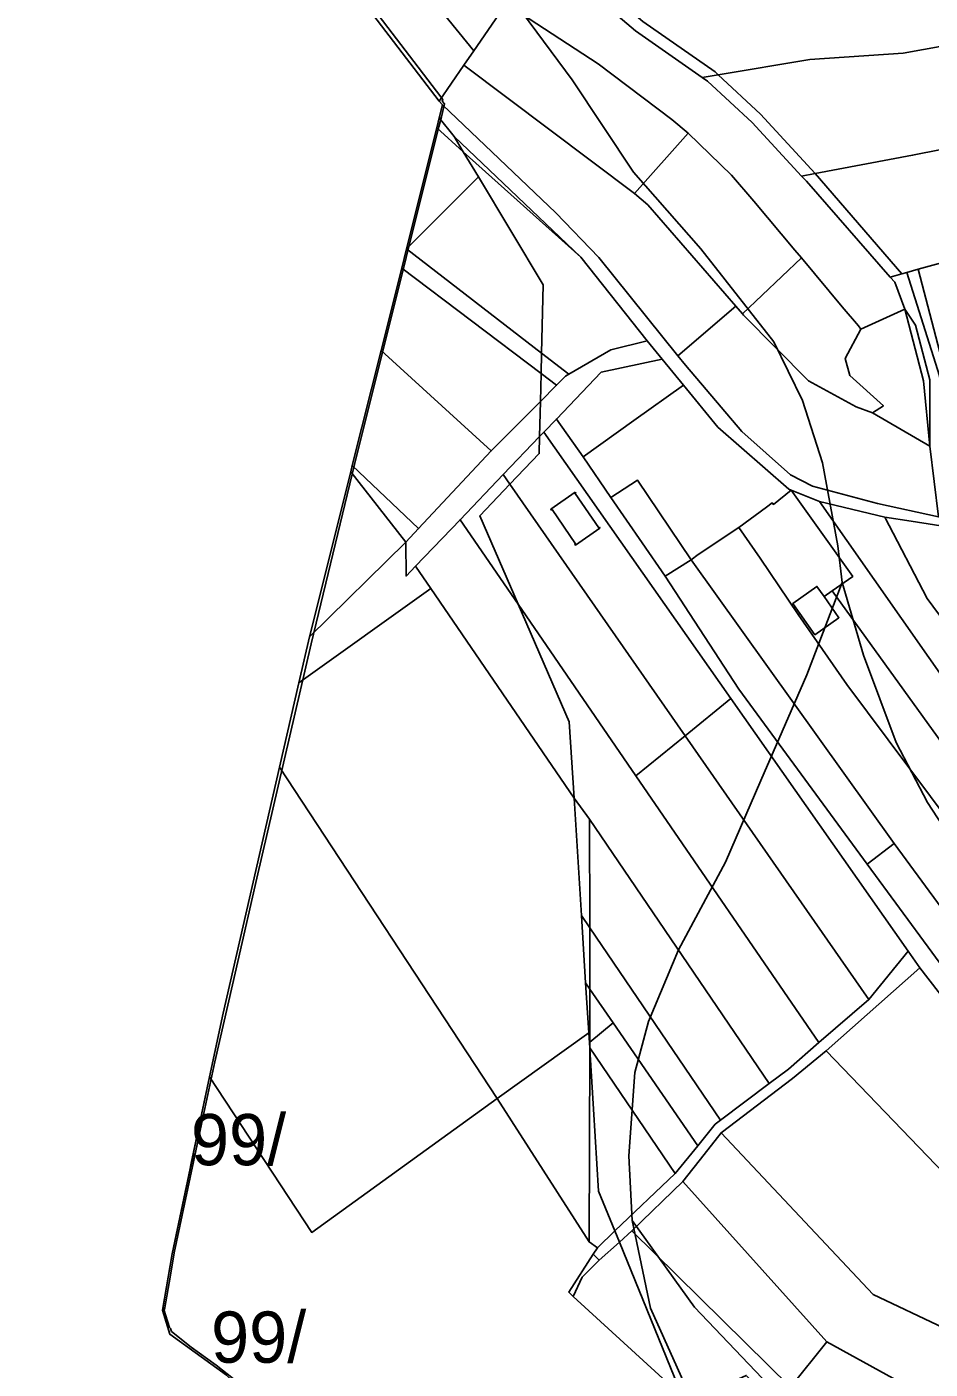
# Model space of a CAD drawing. Extents: x -535894 to -532827, y -1165802 to -1163635.
# Drawn here: x -535269.9 to -535005.1, y -1165464.5 to -1165071.2 of the extents above; entities that cross this region are included whole.
import ezdxf

# ---------------------------------------------------------------- set-up
doc = ezdxf.new("R2010")
doc.units = 0
for name, color, linetype in [('BPEJ_s', 7, 'Continuous'), ('orna_s', 7, 'Continuous'), ('ostatni_s', 7, 'Continuous'), ('sad_s', 7, 'Continuous'), ('trav_porost_s', 7, 'Continuous'), ('zahrada_s', 7, 'Continuous')]:
    doc.layers.add(name, color=color, linetype=linetype)

msp = doc.modelspace()

# ---------------------------------------------------------------- linework, layer by layer
at = {"layer": 'BPEJ_s'}
for points in [[(-535269.853, -1164932.956), (-535148.539, -1165091.751), (-535147.971, -1165092.495), (-535148.097, -1165093.014), (-535147.427, -1165093.765), (-535148.373, -1165097.563), (-535149.117, -1165100.549), (-535157.973, -1165135.942), (-535159.387, -1165141.6), (-535165.434, -1165165.767), (-535173.855, -1165199.418), (-535181.592, -1165231.374), (-535186.572, -1165251.945), (-535202.428, -1165320.572), (-535208.053, -1165345.043), (-535209.623, -1165351.873), (-535214.803, -1165374.411), (-535217.987, -1165389.45), (-535226.653, -1165430.387), (-535227.77, -1165436.903), (-535229.489, -1165446.933), (-535229.697, -1165446.939), (-535229.937, -1165446.154), (-535227.28, -1165430.67), (-535222.616, -1165408.657), (-535220.965, -1165401.364), (-535221.656, -1165404.128), (-535216.3, -1165378.85), (-535212.35, -1165360.19), (-535195.8, -1165288.07), (-535190.12, -1165263.37), (-535187.04, -1165249.93), (-535174.94, -1165201.58), (-535174.47, -1165199.7), (-535166.05, -1165166.05), (-535160, -1165141.88), (-535158.58, -1165136.22), (-535149.73, -1165100.83), (-535148.98, -1165097.84), (-535148.04, -1165094.04), (-535149, -1165092.96), (-535191.37, -1165037.5)], [(-535209.32, -1165467.33), (-535214.364, -1165463.282), (-535221.739, -1165457.976), (-535227.491, -1165453.394), (-535227.757, -1165452.533), (-535228.059, -1165452.29), (-535229.697, -1165446.939), (-535229.489, -1165446.933), (-535227.77, -1165436.903), (-535226.653, -1165430.387), (-535217.987, -1165389.45), (-535214.803, -1165374.411), (-535209.623, -1165351.873), (-535208.053, -1165345.043), (-535202.428, -1165320.572), (-535186.572, -1165251.945), (-535181.592, -1165231.374), (-535173.855, -1165199.418), (-535165.434, -1165165.767), (-535159.387, -1165141.6), (-535157.973, -1165135.942), (-535149.117, -1165100.549), (-535148.373, -1165097.563), (-535147.427, -1165093.765), (-535148.097, -1165093.014), (-535147.971, -1165092.495), (-535148.539, -1165091.751), (-535269.853, -1164932.956)], [(-535032.17, -1165223.23), (-535036.666, -1165198.943), (-535042.52, -1165180.7), (-535050.959, -1165163.5), (-535072.31, -1165136.27), (-535092.06, -1165113.81), (-535110.05, -1165086.73), (-535124.571, -1165067.131)], [(-535124.571, -1165067.131), (-535110.05, -1165086.73), (-535092.06, -1165113.81), (-535072.31, -1165136.27), (-535050.959, -1165163.5), (-535042.52, -1165180.7), (-535036.666, -1165198.943), (-535032.17, -1165223.23), (-535030.89, -1165233.98), (-535041.257, -1165261.04), (-535054.7, -1165292.04), (-535065.06, -1165315.93), (-535078.92, -1165341.58), (-535087.68, -1165362.6), (-535091.66, -1165377.57), (-535093.41, -1165401.94), (-535092.45, -1165420.9), (-535087.04, -1165446.54), (-535075.396, -1165472.696)], [(-535000.001, -1165307.403), (-535005.89, -1165298.41), (-535015.12, -1165280.89), (-535024.68, -1165255.25), (-535030.89, -1165233.98), (-535032.17, -1165223.23)], [(-535054.39, -1165467.13), (-535074.14, -1165446.26), (-535092.45, -1165420.9), (-535093.41, -1165401.94), (-535091.66, -1165377.57), (-535087.68, -1165362.6), (-535078.92, -1165341.58), (-535065.06, -1165315.93), (-535054.7, -1165292.04), (-535041.257, -1165261.04), (-535030.89, -1165233.98), (-535024.68, -1165255.25), (-535015.12, -1165280.89), (-535005.89, -1165298.41), (-535000.001, -1165307.403)], [(-535075.396, -1165472.696), (-535087.04, -1165446.54), (-535092.45, -1165420.9), (-535074.14, -1165446.26), (-535054.39, -1165467.13)]]:
    msp.add_lwpolyline(points, dxfattribs=at)
for points in [[(-535220.965, -1165401.364), (-535222.616, -1165408.657), (-535221.656, -1165404.128)], [(-535197.513, -1165478.818), (-535197.667, -1165478.989), (-535211.33, -1165466.2), (-535227.94, -1165454.25), (-535230.12, -1165447.22), (-535229.937, -1165446.154), (-535229.697, -1165446.939), (-535228.059, -1165452.29), (-535227.757, -1165452.533), (-535227.491, -1165453.394), (-535221.739, -1165457.976), (-535214.364, -1165463.282), (-535209.32, -1165467.33), (-535205.939, -1165470.375), (-535197.241, -1165478.516)]]:
    msp.add_lwpolyline(points, close=True, dxfattribs=at)
at = {"layer": 'orna_s'}
for points in [[(-534688.38, -1164981.11), (-534659.02, -1164979.39), (-534659.81, -1164981.95), (-534655.57, -1165032.56), (-534724.66, -1165029.47), (-534765.23, -1165030.38), (-534811.29, -1165033.87), (-534889.63, -1165046.79), (-534952.44, -1165063.23), (-534984.36, -1165073.72), (-535013.06, -1165078.91), (-535040.34, -1165080.81), (-535067.25, -1165085.28), (-535068.17, -1165084.42), (-535089.33, -1165069.61), (-535106.82, -1165054.65), (-535020.48, -1165037.2), (-534961.7, -1165023.3), (-534911.68, -1165008.4), (-534840.9, -1164993.6), (-534776.34, -1164986.27)], [(-534765.23, -1165030.38), (-534724.66, -1165029.47), (-534655.57, -1165032.56), (-534654.53, -1165060.65), (-534677.01, -1165058.08), (-534733.66, -1165051.62), (-534773.14, -1165052.16), (-534797.08, -1165055.15), (-534876.98, -1165070.12), (-534985.58, -1165103.95), (-535010.28, -1165108.81), (-535038.78, -1165114.13), (-535054.81, -1165096.75), (-535067.25, -1165085.28), (-535040.34, -1165080.81), (-535013.06, -1165078.91), (-534984.36, -1165073.72), (-534952.44, -1165063.23), (-534889.63, -1165046.79), (-534811.29, -1165033.87)], [(-535158.81, -1165222.18), (-535187.04, -1165249.93), (-535174.94, -1165201.58)], [(-535073.16, -1165225.77), (-535061.21, -1165217.88), (-535054.98, -1165226.88), (-535043.78, -1165243.38), (-535029.52, -1165263.9), (-534998.93, -1165304.82), (-534979.45, -1165330.89), (-534948.88, -1165373.43), (-534922.19, -1165413.88), (-534938.7, -1165417.09), (-534970.98, -1165370.34), (-534998.37, -1165333.97), (-535015.67, -1165310.49), (-535075.17, -1165227.4)]]:
    msp.add_lwpolyline(points, close=True, dxfattribs=at)
msp.add_lwpolyline([(-534734.34, -1165074.8), (-534763.47, -1165073.76), (-534794.45, -1165076.97), (-534819.92, -1165081.13), (-534823.22, -1165081.65), (-534869.07, -1165092.98), (-534889.43, -1165100.93), (-534912.55, -1165110.44), (-534943.81, -1165122.47), (-534959.64, -1165128.57), (-534975.01, -1165132.85), (-534993.62, -1165138.05), (-534997.55, -1165139.14), (-535008.66, -1165142.24), (-535012, -1165143.18), (-535013.47, -1165143.59), (-535038.78, -1165114.13), (-535010.28, -1165108.81), (-534985.58, -1165103.95), (-534876.98, -1165070.12)], dxfattribs=at)
at = {"layer": 'ostatni_s'}
for points in [[(-535111.17, -1165055.54), (-535106.82, -1165054.65), (-535089.33, -1165069.61), (-535068.17, -1165084.42), (-535067.25, -1165085.28), (-535071.93, -1165086.06), (-535091.48, -1165072.37)], [(-535071.93, -1165086.06), (-535067.25, -1165085.28), (-535054.81, -1165096.75), (-535038.78, -1165114.13), (-535042.82, -1165114.91), (-535057.29, -1165099.23), (-535070.36, -1165087.15)], [(-535149.73, -1165100.83), (-535148.98, -1165097.84), (-535144.62, -1165103.35), (-535141.94, -1165107.81)], [(-535141.94, -1165107.81), (-535137.53, -1165115.16), (-535158.58, -1165136.22), (-535149.73, -1165100.83)], [(-535042.82, -1165114.91), (-535038.78, -1165114.13), (-535013.47, -1165143.59), (-535016.81, -1165144.52), (-535041.39, -1165116.45)], [(-535158.58, -1165136.22), (-535137.53, -1165115.16), (-535118.55, -1165146.77), (-535119.01, -1165166.82)], [(-535160, -1165141.88), (-535158.58, -1165136.22), (-535119.01, -1165166.82), (-535119.15, -1165172.77)], [(-535166.05, -1165166.05), (-535160, -1165141.88), (-535119.15, -1165172.77), (-535119.34, -1165180.99), (-535133.73, -1165195.47)], [(-535013.47, -1165143.59), (-535012, -1165143.18), (-535002.34, -1165173.49), (-535000.3, -1165193.52), (-534997.45, -1165215.46), (-535000.46, -1165215.04), (-535002.66, -1165214.75), (-535005.25, -1165194.06), (-535005.19, -1165174.65), (-535009.44, -1165158.65), (-535012.56, -1165153.94), (-535015.48, -1165146.04), (-535016.81, -1165144.52)], [(-535025.48, -1165159.77), (-535012.56, -1165153.94), (-535007.1, -1165174.89), (-535005.25, -1165194.06), (-535022.03, -1165184.29), (-535018.83, -1165182.23), (-535028.68, -1165173.31), (-535030.02, -1165168.39)], [(-535009.44, -1165158.65), (-535005.19, -1165174.65), (-535005.25, -1165194.06), (-535007.1, -1165174.89), (-535012.56, -1165153.94)], [(-535098.68, -1165165.83), (-535088.02, -1165163.17), (-535083.66, -1165168.59), (-535101.55, -1165172.42), (-535114.67, -1165186.14), (-535118.3, -1165189.93), (-535119.57, -1165191.26), (-535119.34, -1165180.99), (-535114.59, -1165176.22), (-535111.96, -1165173.57), (-535111, -1165173.01)], [(-535133.73, -1165195.47), (-535155.07, -1165218.2), (-535174.47, -1165199.7), (-535166.05, -1165166.05)], [(-535119.15, -1165172.77), (-535119.01, -1165166.82), (-535111, -1165173.01), (-535111.96, -1165173.57), (-535114.59, -1165176.22)], [(-535077.41, -1165176.22), (-535067.39, -1165188.44), (-535046.59, -1165206.68), (-535045.87, -1165206.9), (-535051.06, -1165211.14), (-535051.41, -1165210.68), (-535053.1, -1165211.91), (-535061.21, -1165217.88), (-535073.16, -1165225.77), (-535075.17, -1165227.4), (-535090.91, -1165203.99), (-535098.68, -1165209.08), (-535106.85, -1165197.19), (-535091.93, -1165186.56)], [(-535119.57, -1165191.26), (-535130.24, -1165202.4), (-535142.88, -1165215.62), (-535155.91, -1165229.23), (-535158.69, -1165232.13), (-535158.81, -1165222.18), (-535155.07, -1165218.2), (-535133.73, -1165195.47), (-535119.34, -1165180.99)], [(-535118.3, -1165189.93), (-535114.67, -1165186.14), (-535106.85, -1165197.19), (-535098.68, -1165209.08), (-535089.57, -1165222.34), (-535082.81, -1165232.15), (-535061.16, -1165265.28), (-535023.58, -1165316.51), (-534995.2, -1165355.23), (-534947.37, -1165418.77), (-534938.7, -1165417.09), (-534922.19, -1165413.88), (-534912.22, -1165410.87), (-534903.47, -1165406.8), (-534899.67, -1165405.03), (-534895.63, -1165410.85), (-534918.48, -1165416.99), (-534950.64, -1165422.73), (-534969.17, -1165397.16), (-535008.17, -1165346.93), (-535011.6, -1165342.03), (-535063.56, -1165267.97)], [(-535174.94, -1165201.58), (-535174.47, -1165199.7), (-535155.07, -1165218.2), (-535158.81, -1165222.18)], [(-535109.14, -1165207.55), (-535108.98, -1165207.79), (-535109.17, -1165207.94), (-535102.27, -1165217.95), (-535102.07, -1165217.82), (-535101.91, -1165218.04), (-535109.09, -1165223.01), (-535109.26, -1165222.75), (-535109.06, -1165222.62), (-535115.94, -1165212.64), (-535116.14, -1165212.77), (-535116.32, -1165212.52)], [(-535051.06, -1165211.14), (-535045.87, -1165206.9), (-535027.81, -1165232.2), (-535033.85, -1165236.42), (-535036.23, -1165238.09), (-535038.3, -1165235.12), (-535045.33, -1165240.11), (-535043.28, -1165243.03), (-535043.78, -1165243.38), (-535054.98, -1165226.88), (-535061.21, -1165217.88), (-535053.1, -1165211.91), (-535051.41, -1165210.68)], [(-535155.91, -1165229.23), (-535142.88, -1165215.62), (-535125.87, -1165240.38), (-535110.91, -1165274.78), (-535109.49, -1165297.17), (-535151.45, -1165235.77)], [(-535158.69, -1165232.13), (-535155.91, -1165229.23), (-535151.45, -1165235.77), (-535190.12, -1165263.37), (-535187.04, -1165249.93), (-535158.81, -1165222.18)], [(-535151.45, -1165235.77), (-535109.49, -1165297.17), (-535107.33, -1165331.56), (-535106.09, -1165351.32), (-535105.18, -1165365.89), (-535131.97, -1165385.19), (-535195.8, -1165288.07), (-535190.12, -1165263.37)], [(-535038.3, -1165235.12), (-535036.23, -1165238.09), (-535031.86, -1165244.32), (-535038.89, -1165249.3), (-535043.28, -1165243.03), (-535045.33, -1165240.11)], [(-535195.8, -1165288.07), (-535131.97, -1165385.19), (-535186.38, -1165424.39), (-535216.3, -1165378.85), (-535212.35, -1165360.19)], [(-535104.97, -1165303.3), (-535104.88, -1165335.18), (-535107.33, -1165331.56), (-535109.49, -1165297.17)], [(-535107.33, -1165331.56), (-535104.88, -1165335.18), (-535104.84, -1165353.15), (-535106.09, -1165351.32)], [(-535011.6, -1165342.03), (-535008.17, -1165346.93), (-535035.57, -1165371.22), (-535045.46, -1165379.26), (-535066.38, -1165395.21), (-535071.39, -1165401.58), (-535077.63, -1165409.51), (-535092.6, -1165423.96), (-535096.21, -1165427.21), (-535097.53, -1165423.98), (-535079.82, -1165407.1), (-535073.24, -1165399.01), (-535068.13, -1165392.72), (-535066.56, -1165391.53), (-535052.32, -1165380.79), (-535046.68, -1165376.54), (-535037.72, -1165368.79), (-535023.08, -1165356.13)], [(-535106.09, -1165351.32), (-535104.84, -1165353.15), (-535104.9, -1165368.65), (-535104.9, -1165370.29), (-535105.18, -1165365.89)], [(-535104.9, -1165370.29), (-535105.08, -1165427.18), (-535131.97, -1165385.19), (-535105.18, -1165365.89)], [(-535131.97, -1165385.19), (-535105.08, -1165427.18), (-535102.66, -1165428.89), (-535103.85, -1165430.74), (-535111.02, -1165441.92), (-535109.7, -1165443.14), (-535077.85, -1165472.41), (-535076.26, -1165476.34), (-535087.18, -1165485.86), (-535153.29, -1165531.56), (-535165.68, -1165517.45), (-535180.07, -1165495.46), (-535211.33, -1165466.2), (-535227.94, -1165454.25), (-535230.12, -1165447.22), (-535227.28, -1165430.67), (-535216.3, -1165378.85), (-535186.38, -1165424.39)], [(-535096.21, -1165427.21), (-535102.15, -1165432.54), (-535103.85, -1165430.74), (-535102.66, -1165428.89), (-535097.53, -1165423.98)]]:
    msp.add_lwpolyline(points, close=True, dxfattribs=at)
msp.add_lwpolyline([(-534998.89, -1165217.93), (-535010.74, -1165216.05), (-535018.41, -1165214.83), (-535037.55, -1165210.25), (-535045.87, -1165206.9), (-535046.59, -1165206.68), (-535067.39, -1165188.44), (-535077.41, -1165176.22), (-535083.66, -1165168.59), (-535088.02, -1165163.17), (-535107.51, -1165138.7), (-535144.62, -1165103.35), (-535148.98, -1165097.84), (-535148.04, -1165094.04), (-535114.86, -1165125.73), (-535102.26, -1165138.81), (-535079.07, -1165167.61), (-535076.86, -1165170.35), (-535060.28, -1165189.76), (-535046.07, -1165202.42), (-535039.58, -1165205.73), (-535020.54, -1165210.89), (-535002.66, -1165214.75)], dxfattribs=at)
at = {"layer": 'sad_s'}
for points in [[(-535037.55, -1165210.25), (-534958.11, -1165323.54), (-534923.85, -1165374.08), (-534903.47, -1165406.8), (-534912.22, -1165410.87), (-534937.49, -1165371.67), (-534989.64, -1165297.88), (-534997.4, -1165286.9), (-535033.85, -1165236.42), (-535027.81, -1165232.2), (-535045.87, -1165206.9)], [(-535018.41, -1165214.83), (-535006.02, -1165238.65), (-534986.55, -1165265), (-534939.83, -1165336.12), (-534921.55, -1165360.67), (-534895.49, -1165403.09), (-534899.67, -1165405.03), (-534903.47, -1165406.8), (-534923.85, -1165374.08), (-534958.11, -1165323.54), (-535037.55, -1165210.25)], [(-535010.74, -1165216.05), (-534998.89, -1165217.93), (-534910.74, -1165344.78), (-534877.22, -1165393.33), (-534885.71, -1165398.12), (-534889.94, -1165400.51), (-534895.49, -1165403.09), (-534921.55, -1165360.67), (-534939.83, -1165336.12), (-534986.55, -1165265), (-535006.02, -1165238.65), (-535018.41, -1165214.83)]]:
    msp.add_lwpolyline(points, close=True, dxfattribs=at)
at = {"layer": 'trav_porost_s'}
for points in [[(-535220.19, -1164916.49), (-535192.57, -1164975.97), (-535181.9, -1164992.48), (-535168.5, -1165015.08), (-535167.09, -1165017.44), (-535153.27, -1165037.38), (-535141.65, -1165049.71), (-535129.39, -1165064.5), (-535138.85, -1165078.22), (-535172.47, -1165036.89), (-535179.28, -1165027.8), (-535211.27, -1164985.05), (-535243.3, -1164928.03), (-535231.36, -1164922.07)], [(-535179.28, -1165027.8), (-535172.47, -1165036.89), (-535138.85, -1165078.22), (-535141.75, -1165082.45), (-535149, -1165092.96), (-535191.37, -1165037.5)], [(-535138.85, -1165078.22), (-535129.39, -1165064.5), (-535102.38, -1165082.03), (-535080.8, -1165098.36), (-535076.07, -1165102.38), (-535091.8, -1165120.03), (-535141.75, -1165082.45)], [(-535141.75, -1165082.45), (-535091.8, -1165120.03), (-535087.88, -1165123.32), (-535062.12, -1165153.01), (-535079.07, -1165167.61), (-535102.26, -1165138.81), (-535114.86, -1165125.73), (-535148.04, -1165094.04), (-535149, -1165092.96)], [(-535141.94, -1165107.81), (-535144.62, -1165103.35), (-535107.51, -1165138.7)], [(-535137.53, -1165115.16), (-535141.94, -1165107.81), (-535107.51, -1165138.7), (-535088.02, -1165163.17), (-535098.68, -1165165.83), (-535111, -1165173.01), (-535119.01, -1165166.82), (-535118.55, -1165146.77)], [(-535060.13, -1165155.29), (-535059.81, -1165155.66), (-535040.74, -1165174.89), (-535026.83, -1165182.51), (-535022.03, -1165184.29), (-535005.25, -1165194.06), (-535002.66, -1165214.75), (-535020.54, -1165210.89), (-535039.58, -1165205.73), (-535046.07, -1165202.42), (-535060.28, -1165189.76), (-535076.86, -1165170.35), (-535079.07, -1165167.61), (-535062.12, -1165153.01)], [(-535119.69, -1165196.25), (-535128.27, -1165205.23), (-535130.24, -1165202.4), (-535119.57, -1165191.26)], [(-535119.57, -1165191.26), (-535118.3, -1165189.93), (-535063.56, -1165267.97), (-535076.93, -1165278.88), (-535128.27, -1165205.23), (-535119.69, -1165196.25)], [(-535128.27, -1165205.23), (-535137.13, -1165214.5), (-535125.87, -1165240.38), (-535142.88, -1165215.62), (-535130.24, -1165202.4)], [(-535090.91, -1165203.99), (-535075.17, -1165227.4), (-535082.81, -1165232.15), (-535089.57, -1165222.34), (-535098.68, -1165209.08)], [(-535137.13, -1165214.5), (-535128.27, -1165205.23), (-535076.93, -1165278.88), (-535091.37, -1165290.64), (-535125.87, -1165240.38)], [(-535109.14, -1165207.55), (-535116.32, -1165212.52), (-535116.14, -1165212.77), (-535115.94, -1165212.64), (-535109.06, -1165222.62), (-535109.26, -1165222.75), (-535109.09, -1165223.01), (-535101.91, -1165218.04), (-535102.07, -1165217.82), (-535102.27, -1165217.95), (-535109.17, -1165207.94), (-535108.98, -1165207.79)], [(-535082.81, -1165232.15), (-535075.17, -1165227.4), (-535015.67, -1165310.49), (-535023.58, -1165316.51), (-535061.16, -1165265.28)], [(-535110.91, -1165274.78), (-535125.87, -1165240.38), (-535091.37, -1165290.64), (-535037.72, -1165368.79), (-535046.68, -1165376.54), (-535052.32, -1165380.79), (-535104.97, -1165303.3), (-535109.49, -1165297.17)], [(-535076.93, -1165278.88), (-535063.56, -1165267.97), (-535011.6, -1165342.03), (-535023.08, -1165356.13)], [(-535091.37, -1165290.64), (-535076.93, -1165278.88), (-535023.08, -1165356.13), (-535037.72, -1165368.79)], [(-535104.88, -1165335.18), (-535104.97, -1165303.3), (-535052.32, -1165380.79), (-535066.56, -1165391.53)], [(-535015.67, -1165310.49), (-534998.37, -1165333.97), (-534970.98, -1165370.34), (-534938.7, -1165417.09), (-534947.37, -1165418.77), (-534995.2, -1165355.23), (-535023.58, -1165316.51)], [(-535104.84, -1165353.15), (-535104.88, -1165335.18), (-535066.56, -1165391.53), (-535068.13, -1165392.72), (-535073.24, -1165399.01), (-535098.04, -1165363.02)], [(-535035.57, -1165371.22), (-535008.17, -1165346.93), (-534969.17, -1165397.16), (-534950.64, -1165422.73), (-534946.88, -1165427.7), (-534976.33, -1165433.85), (-534991.19, -1165417.39)], [(-535104.84, -1165353.15), (-535098.04, -1165363.02), (-535104.9, -1165368.65)], [(-535104.9, -1165368.65), (-535098.04, -1165363.02), (-535073.24, -1165399.01), (-535079.82, -1165407.1), (-535104.9, -1165370.29)], [(-535104.78, -1165372.28), (-535102.28, -1165412.28), (-535097.53, -1165423.98), (-535102.66, -1165428.89), (-535105.08, -1165427.18), (-535104.9, -1165370.29)], [(-535104.78, -1165372.28), (-535104.9, -1165370.29), (-535079.82, -1165407.1), (-535097.53, -1165423.98), (-535102.28, -1165412.28)], [(-535045.46, -1165379.26), (-535035.57, -1165371.22), (-534991.19, -1165417.39), (-534976.33, -1165433.85), (-534971.78, -1165438.88), (-534963.24, -1165444.04), (-534963.38, -1165463.4), (-534980.62, -1165462.08), (-535021.86, -1165442.54), (-535066.38, -1165395.21)], [(-535071.39, -1165401.58), (-535066.38, -1165395.21), (-535021.86, -1165442.54), (-534980.62, -1165462.08), (-534963.38, -1165463.4), (-534962.06, -1165475.26), (-534960.76, -1165486.97), (-534989.98, -1165481.49), (-535035.38, -1165456.43), (-535077.63, -1165409.51)], [(-535092.6, -1165423.96), (-535077.63, -1165409.51), (-535035.38, -1165456.43), (-535046.07, -1165469.78)], [(-535096.21, -1165427.21), (-535092.6, -1165423.96), (-535046.07, -1165469.78), (-535035.38, -1165456.43), (-534989.98, -1165481.49), (-534960.76, -1165486.97), (-534959.91, -1165494.58), (-534953.71, -1165520.27), (-535000.04, -1165522.28), (-535001.7, -1165503.8), (-535042.71, -1165481.75), (-535059.01, -1165466.27), (-535076.09, -1165474.03), (-535077.85, -1165472.41)], [(-535102.15, -1165432.54), (-535096.21, -1165427.21), (-535077.85, -1165472.41), (-535109.7, -1165443.14), (-535107.08, -1165437.55)], [(-535102.15, -1165432.54), (-535107.08, -1165437.55), (-535109.7, -1165443.14), (-535111.02, -1165441.92), (-535103.85, -1165430.74)]]:
    msp.add_lwpolyline(points, close=True, dxfattribs=at)
msp.add_lwpolyline([(-535111.17, -1165055.54), (-535091.48, -1165072.37), (-535071.93, -1165086.06), (-535070.36, -1165087.15), (-535057.29, -1165099.23), (-535042.82, -1165114.91), (-535041.39, -1165116.45), (-535016.81, -1165144.52), (-535015.48, -1165146.04), (-535012.56, -1165153.94), (-535025.48, -1165159.77), (-535026.15, -1165158.85), (-535030.91, -1165153.2), (-535042.84, -1165138.9), (-535044.77, -1165136.59), (-535056.76, -1165122.24), (-535063.36, -1165114.7), (-535076.07, -1165102.38), (-535080.8, -1165098.36), (-535102.38, -1165082.03), (-535129.39, -1165064.5)], dxfattribs=at)
at = {"layer": 'zahrada_s'}
for points in [[(-535076.07, -1165102.38), (-535063.36, -1165114.7), (-535056.76, -1165122.24), (-535044.77, -1165136.59), (-535042.84, -1165138.9), (-535060.13, -1165155.29), (-535062.12, -1165153.01), (-535087.88, -1165123.32), (-535091.8, -1165120.03)], [(-535042.84, -1165138.9), (-535030.91, -1165153.2), (-535026.15, -1165158.85), (-535025.48, -1165159.77), (-535030.02, -1165168.39), (-535028.68, -1165173.31), (-535018.83, -1165182.23), (-535022.03, -1165184.29), (-535026.83, -1165182.51), (-535040.74, -1165174.89), (-535059.81, -1165155.66), (-535060.13, -1165155.29)], [(-535008.66, -1165142.24), (-534997.55, -1165139.14), (-534979.02, -1165176.38), (-534995.45, -1165182.69), (-534993.46, -1165188.33), (-534994.83, -1165188.64), (-534990.02, -1165206.28), (-534988.07, -1165212.89), (-534986.89, -1165216.91), (-534997.45, -1165215.46), (-535000.3, -1165193.52), (-535000.44, -1165173.68), (-535004.66, -1165157.53)], [(-535012, -1165143.18), (-535008.66, -1165142.24), (-535004.66, -1165157.53), (-535000.44, -1165173.68), (-535000.3, -1165193.52), (-535002.34, -1165173.49)], [(-535101.55, -1165172.42), (-535083.66, -1165168.59), (-535077.41, -1165176.22), (-535091.93, -1165186.56), (-535106.85, -1165197.19), (-535114.67, -1165186.14)], [(-535114.59, -1165176.22), (-535119.34, -1165180.99), (-535119.15, -1165172.77)], [(-535033.85, -1165236.42), (-534997.4, -1165286.9), (-534989.64, -1165297.88), (-534998.93, -1165304.82), (-535029.52, -1165263.9), (-535043.78, -1165243.38), (-535043.28, -1165243.03), (-535038.89, -1165249.3), (-535031.86, -1165244.32), (-535036.23, -1165238.09)]]:
    msp.add_lwpolyline(points, close=True, dxfattribs=at)

# ---------------------------------------------------------------- texts
at = {"layer": 'BPEJ_s'}
for p in [(-535221.746, -1165404.716), (-535215.863, -1165462.571)]:
    msp.add_text('99/', height=15, dxfattribs=at).set_placement(p)

doc.saveas('drawing.dxf')
